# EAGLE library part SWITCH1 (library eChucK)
NKK Series M Miniature Toggle Switch Right Angle DPDT
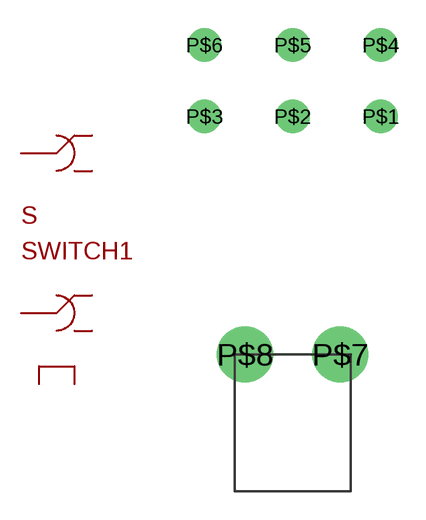
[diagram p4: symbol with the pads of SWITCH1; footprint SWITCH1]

Designator prefix S

## SWITCH1  [SWITCH1]
P$1  P$1
P$2  P$2
P$3  P$3
P$4  P$4
P$5  P$5
P$6  P$6
P$7  P$7
P$8  P$8

## Footprint SWITCH1 (pad centres in mm)
drill 1.2 round: P$1 4.699,12.7; P$2 0,12.7; P$3 -4.699,12.7; P$4 4.699,16.51; P$5 0,16.51; P$6 -4.699,16.51
drill 2 round: P$7 2.54,0; P$8 -2.54,0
